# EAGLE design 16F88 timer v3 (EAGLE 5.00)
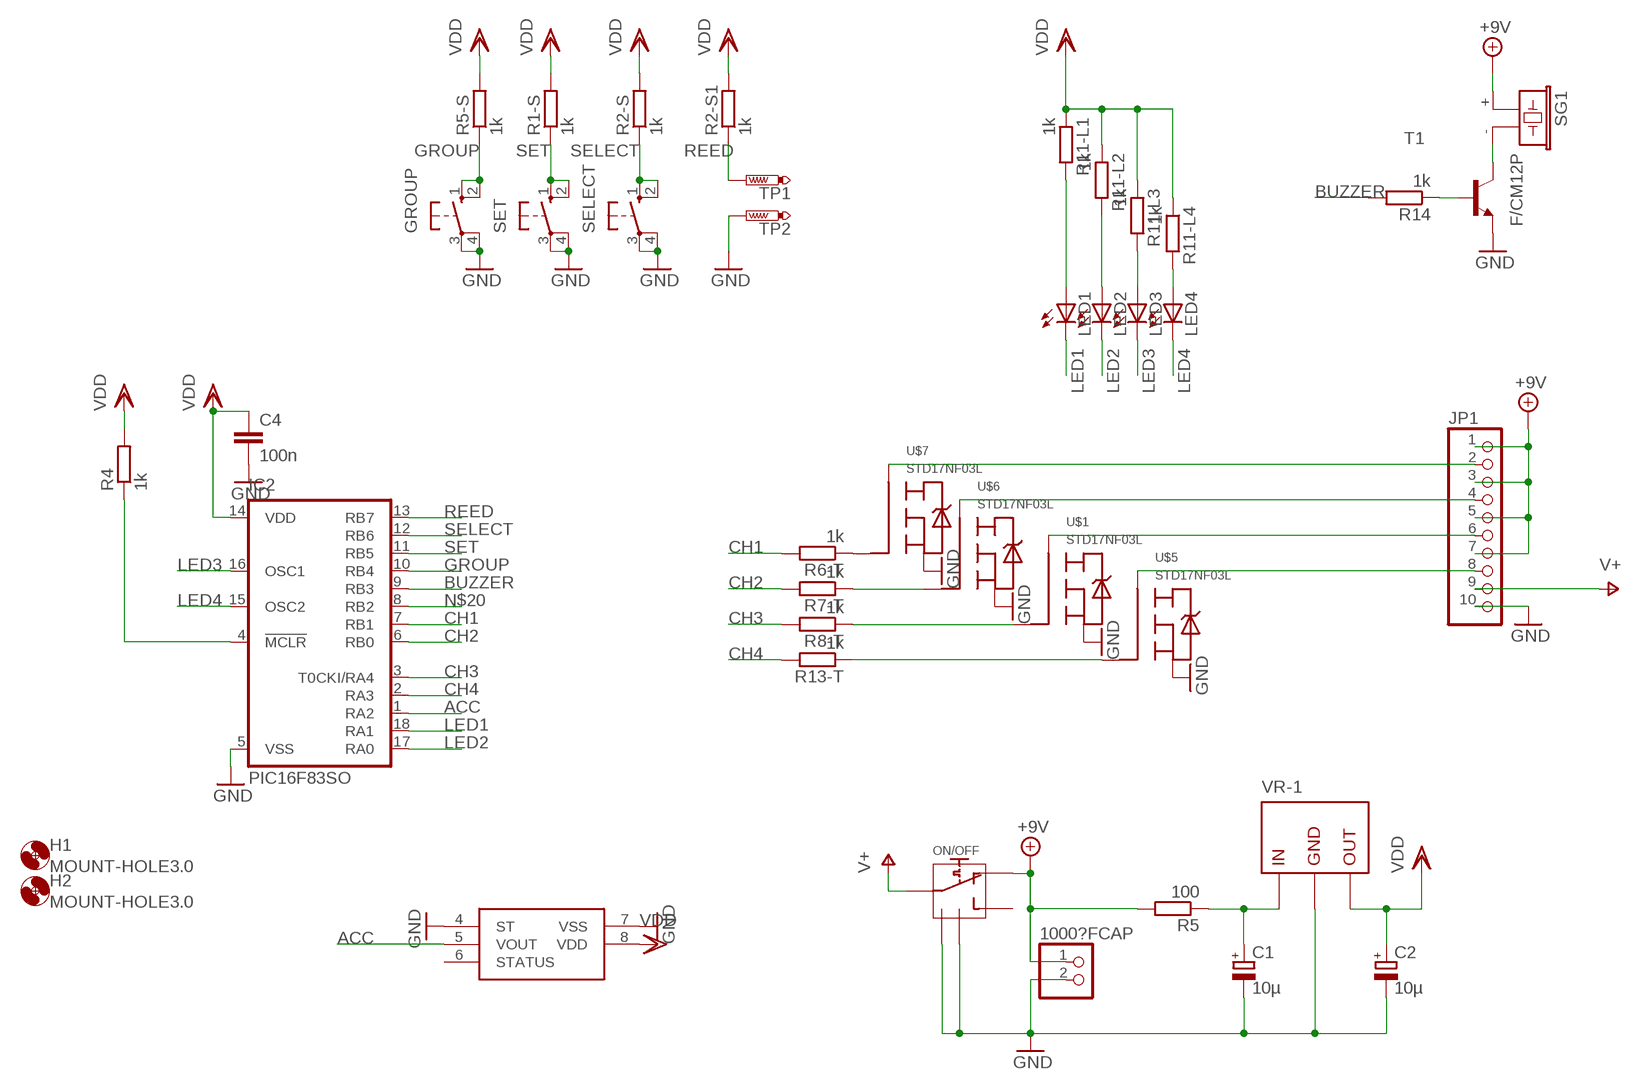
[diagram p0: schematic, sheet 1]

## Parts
1000?FCAP  PINHD-1X2  [1X02]
C1  10µ  CPOL-EUSMCB  [SMC_B]
C2  10µ  CPOL-EUSMCB  [SMC_B]
C4  100n  C-EUC1206  [C1206]
GROUP  10-XX  [B3F-10XX]
H1  MOUNT-HOLE3.0  [3,0]
H2  MOUNT-HOLE3.0  [3,0]
IC2  PIC16F83SO  [SO-18W]
JP1  PINHD-1X10  [1X10]
LED1  LEDCHIPLED_1206  [CHIPLED_1206]
LED2  LEDCHIPLED_1206  [CHIPLED_1206]
LED3  LEDCHIPLED_1206  [CHIPLED_1206]
LED4  LEDCHIPLED_1206  [CHIPLED_1206]
ON/OFF  ON/OFFSWITCH90°A  [PINHEADER1X3]
R1-S  1k  R-EU_R1206W  [R1206W]
R2-S  1k  R-EU_R1206W  [R1206W]
R2-S1  1k  R-EU_R1206W  [R1206W]
R4  1k  R-EU_R1206W  [R1206W]
R5  100  R-EU_R1206W  [R1206W]
R5-S  1k  R-EU_R1206W  [R1206W]
R6-T  1k  R-EU_R1206W  [R1206W]
R7-T  1k  R-EU_R1206W  [R1206W]
R8-T  1k  R-EU_R1206W  [R1206W]
R11-L1  1k  R-EU_R1206W  [R1206W]
R11-L2  1k  R-EU_R1206W  [R1206W]
R11-L3  1k  R-EU_R1206W  [R1206W]
R11-L4  1k  R-EU_R1206W  [R1206W]
R13-T  1k  R-EU_R1206W  [R1206W]
R14  1k  R-EU_R1206W  [R1206W]
SELECT  10-XX  [B3F-10XX]
SET  10-XX  [B3F-10XX]
SG1  F/CM12P  [F/CM12P]
T1  BC847C-NPN-SOT23-BEC  [SOT23-BEC]
TP1  PTR1TP12R  [TP12R]
TP2  PTR1TP12R  [TP12R]
U$1  STD17NF03L  [D-PAK]
U$2  MMA2202D  [SO16W]
U$5  STD17NF03L  [D-PAK]
U$6  STD17NF03L  [D-PAK]
U$7  STD17NF03L  [D-PAK]
VR-1  LC50CDT  [LC50CDT]

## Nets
+9V: 1000?FCAP.1 JP1.1 JP1.3 JP1.5 JP1.7 ON/OFF.NC R5.2 SG1.+
ACC: IC2.1(RA2) U$2.5(VOUT)
BUZZER: IC2.9(RB3) R14.2
CH1: IC2.7(RB1) R6-T.2
CH2: IC2.6(RB0) R7-T.2
CH3: IC2.3(T0CKI/RA4) R8-T.2
CH4: IC2.2(RA3) R13-T.2
GND: 1000?FCAP.2 C1.- C2.- C4.2 GROUP.3(P) GROUP.4(P1) IC2.5(VSS) JP1.10 ON/OFF.GND1 ON/OFF.GND2 SELECT.3(P) SELECT.4(P1) SET.3(P) SET.4(P1) T1.E TP2.TP U$1.P$3 U$2.4(ST) U$2.7(VSS) U$5.P$3 U$6.P$3 U$7.P$3 VR-1.GND
GROUP: GROUP.1(S) GROUP.2(S1) IC2.10(RB4) R5-S.1
LED1: IC2.18(RA1) LED1.C
LED2: IC2.17(RA0) LED2.C
LED3: IC2.16(OSC1) LED3.C
LED4: IC2.15(OSC2) LED4.C
MCLR: IC2.4(!MCLR) R4.1
N$1: LED4.A R11-L4.2
N$3: JP1.8 U$5.P$2
N$4: JP1.2 U$7.P$2
N$5: JP1.6 U$1.P$2
N$6: JP1.4 U$6.P$2
N$7: R13-T.1 U$5.P$1
N$8: R8-T.1 U$1.P$1
N$9: R7-T.1 U$6.P$1
N$10: R6-T.1 U$7.P$1
N$13: C1.+ R5.1 VR-1.IN
N$20: IC2.8(RB2)
N$26: LED1.A R11-L1.2
N$27: LED2.A R11-L2.2
N$28: LED3.A R11-L3.2
N$31: SG1.- T1.C
N$33: R14.1 T1.B
REED: IC2.13(RB7) R2-S1.1 TP1.TP
SELECT: IC2.12(RB6) R2-S.1 SELECT.1(S) SELECT.2(S1)
SET: IC2.11(RB5) R1-S.1 SET.1(S) SET.2(S1)
V+: JP1.9 ON/OFF.COM
VDD: C2.+ C4.1 IC2.14(VDD) R1-S.2 R2-S1.2 R2-S.2 R4.2 R5-S.2 R11-L1.1 R11-L2.1 R11-L3.1 R11-L4.1 U$2.8(VDD) VR-1.OUT
Unconnected: ON/OFF.NO U$2.6(STATUS)

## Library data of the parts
1000?FCAP = pinhead:PINHD-1X2: PIN HEADER
C1 C2 = rcl:CPOL-EU: POLARIZED CAPACITOR, European symbol
C4 = rcl:C-EU: CAPACITOR, European symbol
GROUP SELECT SET = switch-omron:10-XX: OMRON SWITCH
H1 H2 = holes:MOUNT-HOLE: MOUNTING HOLE with drill center marker
IC2 = microchip:PIC16F8*: MICROCONTROLLER 8-Bit PIC16F8X Family - CMOS Flash/EEPROM Pin Compatible : PIC16F83, PIC16CR83, PIC16F84A, PIC16CR84 see also PIC16C*
JP1 = pinhead:PINHD-1X10: PIN HEADER
LED1-LED4 = led:LED: LED
ON/OFF = David Steeman:ON/OFFSWITCH90°
R1-S R2-S R2-S1 R4 R5 R5-S R6-T R7-T R8-T R11-L1-R11-L4 R13-T R14 = rcl:R-EU_: RESISTOR, European symbol
SG1 = buzzer:F/CM12P: BUZZER
T1 = transistor:*-NPN-: NPN Transistror
TP1 TP2 = testpad:PTR1: TEST PIN
U$1 U$5-U$7 = David Steeman:STD17NF03L
U$2 = mma2202d:MMA2202D
VR-1 = David Steeman:LC50CDT: SMD 5V regulator

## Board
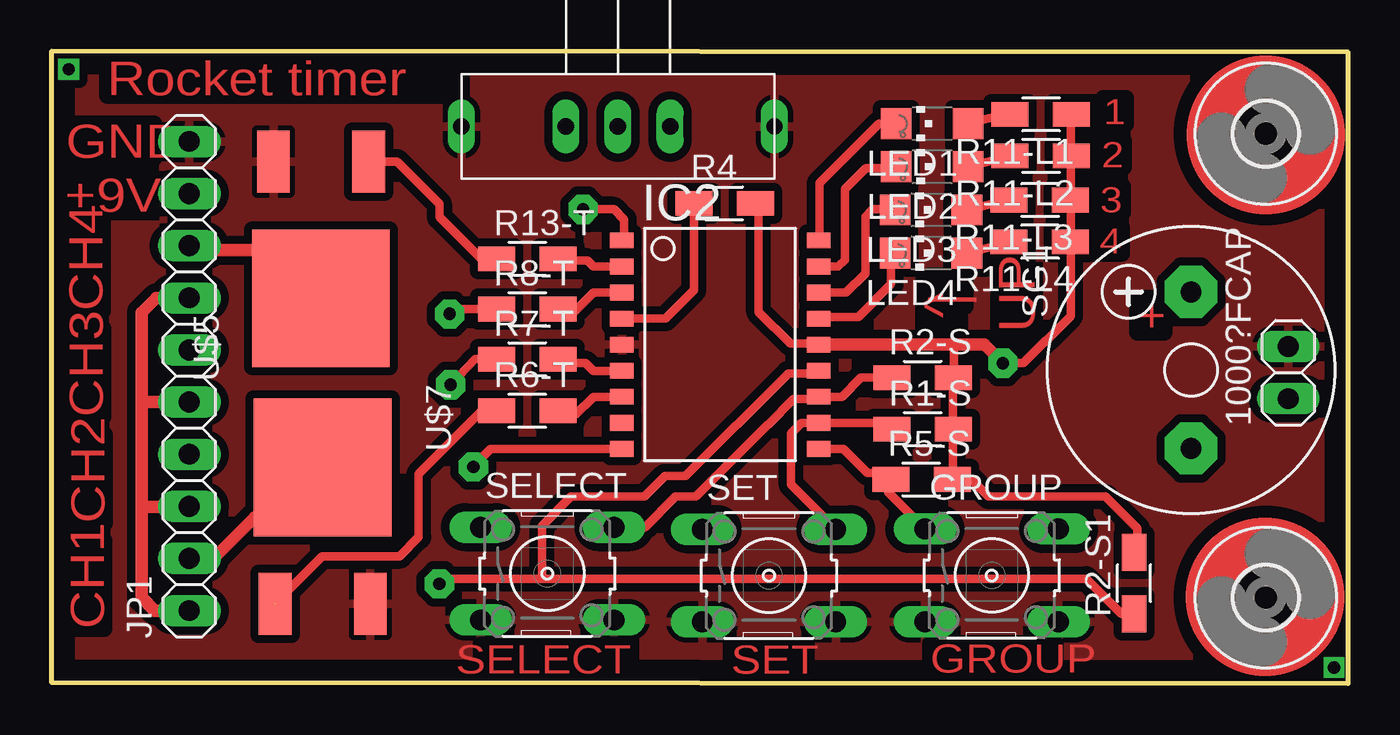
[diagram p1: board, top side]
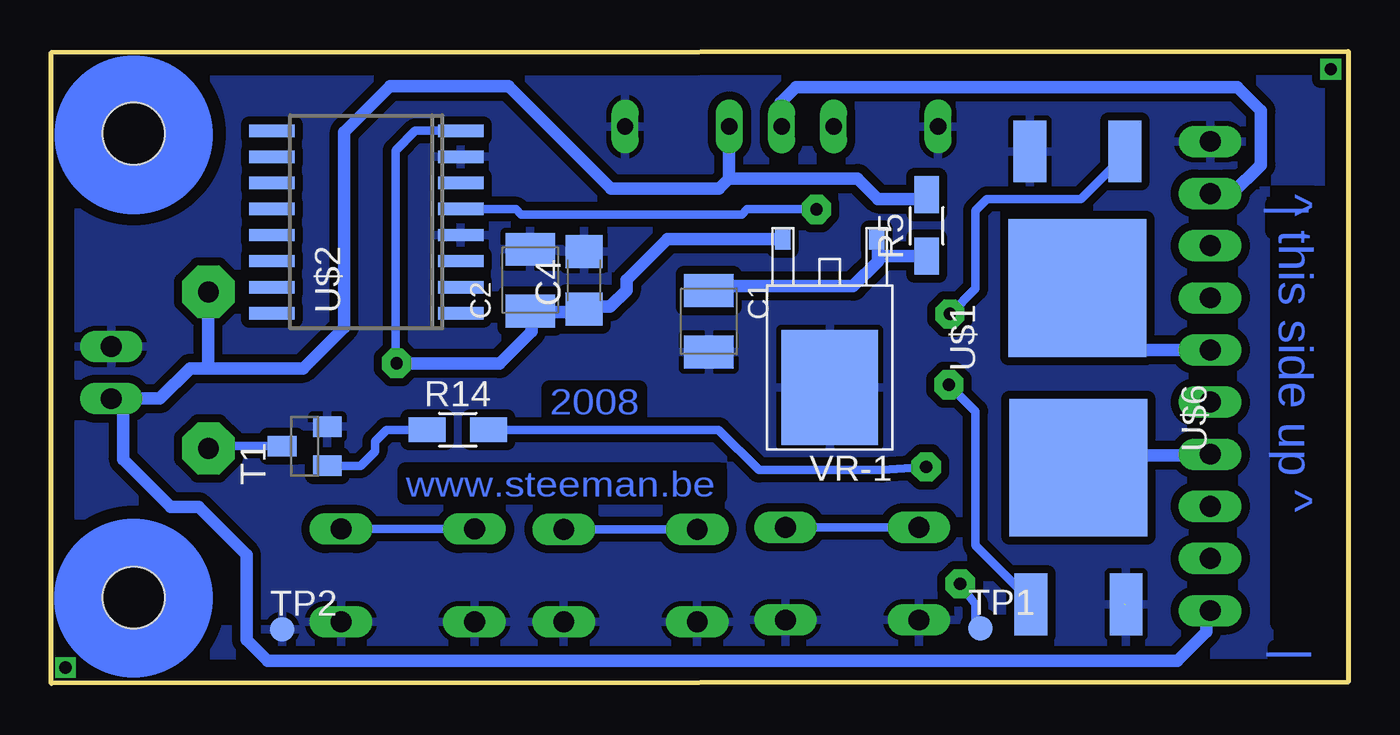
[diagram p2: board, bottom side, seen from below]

Size 63.16 x 30.79 mm. Coordinates in mm from the lower left corner, seen from the top.
Outline: 0,0.05 63.16,0 63.16,30.74 0,30.79 0,0.05
Copper layers (1*16): Top 0.035mm / dielectric 1.5mm / Bottom 0.035mm
Design rules "default": minimum track width 10mil, minimum drill 24mil, track to track 8mil, track to pad 8mil, pad to pad 8mil, via to via 8mil, smd to smd 8mil, copper to edge 40mil, drill to drill 8mil, minimum pad ring 10mil, minimum via ring 8mil, stop-mask expansion 4mil, vias tented up to drill 0mil, thermal gap 10mil

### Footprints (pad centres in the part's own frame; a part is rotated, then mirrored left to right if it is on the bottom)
1X02 = drill 1.016 long: 1 -1.27,0; 2 1.27,0
SMC_B = smd 1.6 x 2.4: + -1.5,0; - 1.5,0
C1206 = smd 1.6 x 1.8: 1 -1.4,0; 2 1.4,0
B3F-10XX = drill 1.016 long: 1 -3.251,2.261; 2 3.251,2.261; 3 -3.251,-2.261; 4 3.251,-2.261
3,0 = hole 3: 0,0
SO-18W = smd 0.762 x 1.143: 1 -5.08,-4.788; 2 -3.81,-4.788; 3 -2.54,-4.788; 4 -1.27,-4.788; 5 0,-4.788; 6 1.27,-4.788; 7 2.54,-4.788; 8 3.81,-4.788; 9 5.08,-4.788; 10 5.08,4.788; 11 3.81,4.788; 12 2.54,4.788; 13 1.27,4.788; 14 0,4.788; 15 -1.27,4.788; 16 -2.54,4.788; 17 -3.81,4.788; 18 -5.08,4.788
1X10 = drill 1.016 long: 1 -11.43,0; 2 -8.89,0; 3 -6.35,0; 4 -3.81,0; 5 -1.27,0; 6 1.27,0; 7 3.81,0; 8 6.35,0; 9 8.89,0; 10 11.43,0
CHIPLED_1206 = smd 1.5 x 1.5: A 0,-1.75; C 0,1.75
PINHEADER1X3 = drill 0.8 long: COM 0,0; GND1 -7.62,0; GND2 7.62,0; NC 2.54,0; NO -2.54,0
R1206W = smd 1.8 x 1.2: 1 -1.499,0; 2 1.499,0
F/CM12P = drill 1.016 pad 2.54 octagon: + 3.81,0; - -3.81,0
SOT23-BEC = smd 1 x 1.4: B -0.95,-1.1; C 0,1.1; E 0.95,-1.1
TP12R = smd 1.2 x 1.2: TP 0,0
D-PAK = smd 3 x 1.6: P$1 3.31,-2.3; P$3 3.31,2.34 | smd 6.7 x 6.7: P$2 -3.34,0.02
SO16W = smd 0.6 x 2.2: 1 -4.445,-4.6; 2 -3.175,-4.6; 3 -1.905,-4.6; 4 -0.635,-4.6; 5 0.635,-4.6; 6 1.905,-4.6; 7 3.175,-4.6; 8 4.445,-4.6; 9 4.445,4.6; 10 3.175,4.6; 11 1.905,4.6; 12 0.635,4.6; 13 -0.635,4.6; 14 -1.905,4.6; 15 -3.175,4.6; 16 -4.445,4.6
LC50CDT = smd 4.699 x 5.588: GND 0,3.454 | smd 0.762 x 1.016: IN -2.286,-3.785; OUT 2.286,-3.785

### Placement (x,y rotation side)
1000?FCAP  60.25,15.13 90 top
C1  31.14,17.63 270 bottom
C2  39.84,19.64 90 bottom
C4  37.21,19.63 90 bottom
GROUP  45.8,5.26 0 top
H1  59.15,26.78 0 top
H2  59.15,4.18 0 top
IC2  32.58,16.49 270 top
JP1  6.72,14.97 90 top
LED1  42.9,27.27 90 top
LED2  42.9,25.16 90 top
LED3  42.85,23.06 90 top
LED4  42.85,20.96 90 top
ON/OFF  27.6,27.12 0 top
R1-S  42.44,12.38 0 top
R2-S  42.44,14.88 0 top
R2-S1  52.73,4.88 90 top
R4  32.79,23.38 0 top
R5  20.53,22.3 90 bottom
R5-S  42.39,9.94 0 top
R6-T  23.19,13.29 0 top
R7-T  23.19,15.79 0 top
R8-T  23.19,18.23 0 top
R11-L1  48.18,27.71 180 top
R11-L2  48.18,25.69 180 top
R11-L3  48.13,23.54 180 top
R11-L4  48.13,21.52 180 top
R13-T  23.19,20.68 0 top
R14  43.36,12.36 0 bottom
SELECT  24.15,5.34 0 top
SET  34.95,5.25 0 top
SG1  55.51,15.26 90 top
T1  50.82,11.56 90 bottom
TP1  17.92,2.69 0 bottom
TP2  51.92,2.64 0 bottom
U$1  13.17,22.59 90 bottom
U$2  47.82,22.47 90 bottom
U$5  13.16,22.11 90 top
U$6  13.16,7.16 270 bottom
U$7  13.2,7.18 270 top
VR-1  25.25,17.86 180 bottom

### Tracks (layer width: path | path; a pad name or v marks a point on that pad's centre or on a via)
+9V
  Top 0.61: JP1.1 5.04,3.54 4.4,4.18 4.4,8.6 | JP1.3 6.65,8.62 6.65,8.6 4.4,8.6 | 4.4,8.6 4.4,14.1 | 4.4,14.1 4.4,18.07 5.11,18.78 JP1.7 | JP1.5 4.4,13.7 4.4,14.1
  Bottom 0.406: ON/OFF.NC | 20.65,23.8 20.65,23.84 | 20.65,23.8 R5.2 | 20.65,23.59 20.65,23.8
  Bottom 0.61: 55.52,15.35 56.4,15.35 57.88,13.87 1000?FCAP.1 59.65,13.87 59.65,10.9 57.34,8.6 55.99,8.6 53.65,6.25 53.65,2.13 52.62,1.09 8.31,1.09 6.9,2.51 6.9,3.54 JP1.1 | 55.52,15.35 50.9,15.35 48.9,17.34 48.9,26.86 46.66,29.09 40.9,29.09 35.9,24.09 30.65,24.09 30.15,24.59 | 30.15,24.59 ON/OFF.NC | 20.65,23.59 22.9,23.59 23.9,24.59 30.15,24.59 | SG1.+ 55.52,19.07 55.52,15.35
ACC  (via drill 0.6 pad 1.42)
  Top 0.406: IC2.1 27.9,21.57 27.9,22.59 27.4,23.09 v25.9,23.09
  Bottom 0.406: 43.4,23.09 43.4,23.11 U$2.5 43.15,23.11 43.15,23.09 40.52,23.09 40.27,22.84 29.52,22.84 29.27,23.09 v25.9,23.09
BUZZER  (via drill 0.6 pad 1.42)
  Top 0.406: IC2.9 21.4,11.42 v20.55,10.54
  Bottom 0.406: R14.2 30.66,12.36 28.7,10.4 22.7,10.4 v20.55,10.54
CH1
  Top 0.406: IC2.7 26.4,13.96 25.54,13.1 24.9,13.1 24.9,13.29 R6-T.2
CH2
  Top 0.406: IC2.6 26.4,15.23 26.03,15.6 24.9,15.6 24.9,15.79 R7-T.2
CH3
  Top 0.406: IC2.3 26.4,19.04 25.46,18.09 24.4,18.09 24.4,18.23 R8-T.2
CH4
  Top 0.406: IC2.2 26.4,20.3 26.11,20.59 24.4,20.59 24.4,20.68 R13-T.2
GND
  pour Top (isolate 0.406): 0.1,30.48 63.51,30.48 63.51,0.46 0.1,0.46
  pour Bottom (isolate 0.406): -0.9,31.48 64.01,31.48 64.01,-1.54 -0.9,-1.54
GROUP
  Top 0.406: GROUP.1 40.75,9.32 40.75,10.25 40.9,10.25 | 40.9,10.25 40.85,10.25 40.85,10.29 R5-S.1 40.9,10.29 40.9,10.25 | IC2.10 38.58,11.42 39.75,10.25 40.9,10.25
  Bottom 0.406: 49.1,7.52 GROUP.2 | GROUP.1 49.1,7.52 | 49.1,7.52 49.1,7.54
LED1
  Top 0.406: IC2.18 37.4,21.57 37.4,24.36 40.3,27.27 LED1.C
LED2
  Top 0.406: LED2.C 41.15,25.09 39.68,25.09 38.65,24.06 38.65,20.63 38.32,20.3 IC2.17
LED3
  Top 0.406: LED3.C 41.15,23.06 41.15,23.09 40,23.09 39.65,22.74 39.65,22.59 | IC2.16 38.71,19.04 39.65,19.97 39.65,22.59 | 39.65,22.59 39.65,22.64
LED4
  Top 0.406: LED4.C 40.9,20.96 40.9,19.45 39.3,17.84 37.4,17.84 37.4,17.77 IC2.15
MCLR
  Top 0.406: R4.1 31.3,23.45 | R4.1 | IC2.4 29.91,17.77 31.3,19.15 R4.1
N$1
  Top 0.406: R11-L4.2 46.65,21.59 | R11-L4.2 | LED4.A 46.65,21.46 R11-L4.2
N$3
  Top 0.406: 11.9,18.77 U$5.P$2 | JP1.8 6.75,21.32
  Top 0.61: 11.9,18.77 11.9,21.09 6.75,21.09 6.75,21.32
N$4
  Top 0.406: 11.9,8.1 11.9,10.52 | 6.65,6.08 6.65,5.94 | JP1.2 6.65,6.08 | 6.65,6.08 6.65,6.09
  Top 0.61: 11.9,10.52 U$7.P$2 | 11.9,8.1 9.9,8.1 7.9,6.09 6.65,6.09
N$5
  Bottom 0.61: 13.4,19.25 13.4,19.59 | 13.4,19.25 U$1.P$2 | JP1.6 13.4,16.24 13.4,19.25
N$6
  Bottom 0.406: U$6.P$2 11.9,10.55 11.9,11.1 | 6.9,11.1 6.9,11.16 JP1.4
  Bottom 0.61: 6.9,11.1 11.9,11.1
N$7
  Top 0.406: U$5.P$1 16.83,25.42 18.9,23.35 18.9,22.71 21.02,20.59 21.4,20.59 21.4,20.68 R13-T.1
N$8  (via drill 0.6 pad 1.42)
  Top 0.406: 19.4,17.95 v19.4,17.99 19.4,18.23 R8-T.1
  Bottom 0.406: 10.71,25.9 13.02,23.59 17.59,23.59 18.15,23.04 18.15,19.22 19.4,17.97 v19.4,17.99
  Bottom 0.61: U$1.P$1 10.71,25.9
N$9  (via drill 0.6 pad 1.42)
  Top 0.406: v19.45,14.54 20.65,15.79 21.65,15.79 | 21.65,15.79 R7-T.1 | 21.65,15.79 21.65,15.85
  Bottom 0.406: 15.4,3.85 | 15.4,3.85 15.4,3.72 | U$6.P$1 15.4,3.85 | v19.45,14.54 18.15,13.25 18.15,6.72 15.4,3.97 15.4,3.85
N$10  (1 unrouted)
  Top 0.406: 10.85,3.85 13.2,6.19 16.96,6.19 17.9,7.13 17.9,10.2 20.99,13.29 R6-T.1
N$11
  pour Top (isolate 0.406): -0.1,31.09 63.9,31.09 63.9,0.1 -0.1,0.1
N$12
  pour Bottom (isolate 0.406): -0.1,31.09 63.4,31.09 63.9,-0.91 -0.1,-0.91
N$13
  Bottom 0.406: 22.9,20.81 22.9,20.84
  Bottom 0.61: VR-1.IN 22.9,21.65 22.9,20.84 22.9,20.56 24.11,19.34 31.15,19.34 C1.+ | C1.+ 31.15,19.09 | C1.+ | R5.1 22.9,20.81
N$15  (via drill 0.6)
  other vias: 62.47,0.77
N$16  (via drill 0.6)
  other vias: 0.84,29.92
N$26
  Top 0.406: 46.65,27.71 46.65,27.59 | 46.65,27.71 R11-L1.2 | LED1.A 46.65,27.77 46.65,27.71
N$27
  Top 0.406: 46.65,25.66 46.65,25.69 R11-L2.2 | LED2.A 46.65,25.66 | 46.65,25.66 46.65,25.59
N$28
  Top 0.406: 46.65,23.56 R11-L3.2 | LED3.A 46.65,23.56 | 46.65,23.56 46.65,23.59
N$31
  Bottom 0.406: 55.4,11.95 55.4,12.1 | 55.4,11.95 SG1.- | T1.C 55.4,11.56 55.4,11.95
N$33
  Bottom 0.406: R14.1 46.84,12.36 47.4,11.79 47.4,11.3 48.11,10.6 49.9,10.6 49.9,10.61 T1.B
REED  (via drill 0.6 pad 1.42)
  Top 0.406: R2-S1.1 52.11,3.39 50.4,5.09 23.9,5.09 | 23.9,5.09 23.9,7.68 25.31,9.1 28.9,9.1 29.9,10.1 30.9,10.1 35.9,15.1 37.4,15.1 37.4,15.23 | 23.9,5.09 18.9,5.09 v18.9,4.84 | 37.4,15.23 37.4,15.35 | 37.4,15.23 IC2.13
  Bottom 0.406: 18.15,2.94 18.15,2.85 | TP1.TP 18.15,2.94 | 18.15,2.94 18.15,3.85 v18.9,4.84
SELECT
  Top 0.406: 41.05,14.88 41.05,14.85 | 41.05,14.88 R2-S.1 | 41.05,14.88 41.05,14.9 39.44,14.9 38.5,13.96 IC2.12 37.4,13.96 | SELECT.2 28.91,7.6 30.4,9.1 31.39,9.1 34.9,12.61 34.9,12.6 36.15,13.85 37.4,13.85 37.4,13.96 | 37.4,13.96 37.4,14.1
  Bottom 0.406: SELECT.1 SELECT.2
SET
  Top 0.406: 40.75,12.69 IC2.11 36.53,12.69 36.02,12.18 36.02,9.69 SET.2 | 40.75,12.69 40.9,12.69 40.9,11.95 | R1-S.1 40.75,12.38 40.75,12.69
  Bottom 0.406: SET.1 | SET.1 SET.2 | SET.1
V+
  Bottom 0.406: 27.65,27.09 27.65,27.12 ON/OFF.COM
  Bottom 0.61: JP1.9 6.75,23.86 6.75,23.84 5.66,23.84 4.25,25.25 4.25,27.89 5.4,29.04 26.9,29.04 27.65,28.29 27.65,27.12
VDD  (via drill 0.6 pad 1.42)
  Top 0.406: 43.9,12.38 R5-S.2 44.81,9.94 45.65,9.1 51.34,9.1 52.9,7.54 52.9,7.13 R2-S1.2 | 43.9,12.38 R1-S.2 | 43.9,12.38 43.9,14.88 R2-S.2 43.95,16.49 43.9,16.49 | 46.68,15.7 46.4,15.7 46.4,15.6 | R4.2 34.45,23.38 34.45,18.1 36,16.54 37.5,16.54 37.5,16.49 | 49.65,25.69 49.65,25.59 | R11-L1.1 49.65,27.71 49.65,25.69 | 49.65,23.54 R11-L3.1 | 49.65,25.69 R11-L2.1 | 49.65,23.54 49.65,25.69 | v46.35,15.6 46.4,15.6 | 46.4,15.6 47.34,15.6 49.65,17.9 49.65,21.52 | 49.65,21.52 R11-L4.1 | 49.65,21.52 49.65,23.54
  Top 0.61: v46.35,15.6 45.45,16.49 43.95,16.49 37.5,16.49 IC2.14
  Bottom 0.406: v46.35,15.6 46.4,15.6 46.4,25.95 45.43,26.92 U$2.8
  Bottom 0.61: v46.35,15.6 46.37,15.57 41.33,15.57 39.77,17.13 39.77,18.14 C2.+ 39.9,18.14 | VR-1.OUT 33.15,21.65 35.15,19.65 35.15,19.14 35.94,18.34 37.15,18.34 | 37.15,18.34 37.15,18.23 | 39.9,18.14 39.9,18.34 | 39.9,18.14 39.9,18.09 37.15,18.09 | 37.15,18.23 37.15,18.09 | 37.15,18.23 C4.1 | 37.15,18.34 37.15,18.09
(copper drawn outside any net)
  shapes: Bottom circle x2, Top circle x2

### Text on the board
Top: Rocket timer | 1 | 2 | GND | 3 | +9V | 4 | CH4 | ^ | | | UP | + | CH3 | CH2 | CH1 | SELECT | SET | GROUP
Bottom: ^ this side up ^ | | | 2008 | www.steeman.be | |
